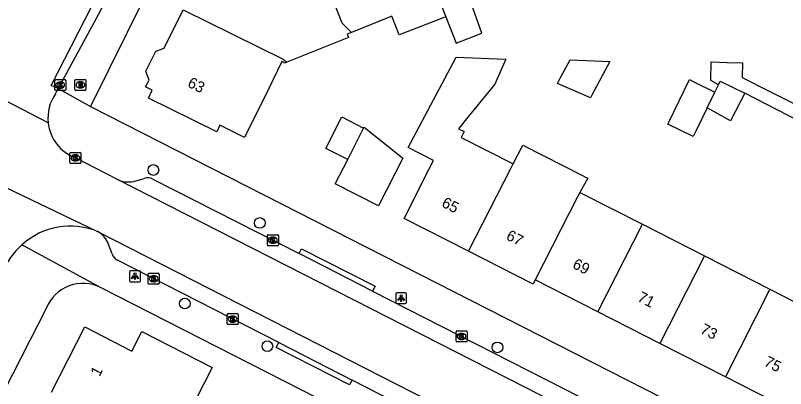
# Model space of a CAD drawing. Extents: x 160356 to 161355, y 381727 to 382845.
# Drawn here: x 161153.1 to 161223.5, y 382295.8 to 382329.8 of the extents above; entities that cross this region are included whole.
import ezdxf

# ---------------------------------------------------------------- set-up
doc = ezdxf.new("R2010")
doc.units = 0
for name, color, linetype in [('IMGEO_Boom', 7, 'Continuous'), ('IMGEO_Brandkraan', 7, 'Continuous'), ('IMGEO_Kolk', 7, 'Continuous'), ('IMGEO_Lichtpunt', 7, 'Continuous'), ('IMGEO_Pand', 7, 'Continuous'), ('IMGEO_Pand_nummerreeks', 7, 'Continuous'), ('IMGEO_Rijbaan_lokaal_open', 7, 'Continuous'), ('IMGEO_Voetpad_open', 7, 'Continuous')]:
    doc.layers.add(name, color=color, linetype=linetype)

msp = doc.modelspace()

# ---------------------------------------------------------------- linework, layer by layer
at = {"layer": 'IMGEO_Boom'}
for centre in [(161165.74, 382315.723), (161175.464, 382310.884), (161168.612, 382303.527), (161176.157, 382299.63), (161197.188, 382299.521)]:
    msp.add_circle(centre, 0.489, dxfattribs=at)
at = {"layer": 'IMGEO_Brandkraan'}
for p, q in [((161158.569, 382323.071), (161158.569, 382323.923)), ((161158.644, 382323.997), (161159.496, 382323.997)), ((161159.057, 382323.777), (161159.082, 382323.777)), ((161159.57, 382323.923), (161159.57, 382323.071)), ((161159.496, 382322.997), (161158.644, 382322.997)), ((161159.08, 382323.217), (161159.055, 382323.217))]:
    msp.add_line(p, q, dxfattribs=at)
for points in [[(161158.569, 382323.071), (161158.569, 382323.923)], [(161158.644, 382323.997), (161159.496, 382323.997)], [(161158.917, 382323.697), (161158.917, 382323.297), (161159.13, 382323.297)], [(161159.148, 382323.697), (161158.917, 382323.697)], [(161159.57, 382323.923), (161159.57, 382323.071)], [(161159.496, 382322.997), (161158.644, 382322.997)], [(161159.096, 382323.616), (161159.042, 382323.616), (161159.042, 382323.54)], [(161159.042, 382323.54), (161159.095, 382323.54)], [(161159.104, 382323.464), (161159.042, 382323.464), (161159.042, 382323.383)], [(161159.042, 382323.383), (161159.104, 382323.383)]]:
    msp.add_lwpolyline(points, dxfattribs=at)
for centre, radius, start, end in [((161158.646, 382323.921), 0.0765, 91.55205, 178.44795), ((161158.646, 382323.921), 0.0765, 91.55205, 178.44795), ((161159.152, 382323.552), 0.145, 59.4692, 91.53667), ((161159.177, 382323.599), 0.0922, 285.51372, 58.15012), ((161159.494, 382323.921), 0.0765, 1.55205, 88.44795), ((161159.494, 382323.921), 0.0765, 1.55205, 88.44795), ((161158.646, 382323.073), 0.0765, 181.55205, 268.44795), ((161158.646, 382323.073), 0.0765, 181.55205, 268.44795), ((161159.097, 382323.578), 0.0379, 267.82845, 90.93552), ((161159.105, 382323.423), 0.0404, 269.87594, 90.50774), ((161159.136, 382323.548), 0.251, 268.66757, 293.53466), ((161159.182, 382323.407), 0.105, 301.31148, 78.98903), ((161159.494, 382323.073), 0.0765, 271.55205, 358.44795), ((161159.494, 382323.073), 0.0765, 271.55205, 358.44795)]:
    msp.add_arc(centre, radius, start, end, dxfattribs=at)
for centre, major_axis, ratio, start_param, end_param in [((161159.056, 382323.497), (-0.387, 0.002), 0.722429, 4.712389, 7.853982), ((161159.081, 382323.497), (-0.39, 0.002), 0.717154, 1.570796, 4.712389)]:
    msp.add_ellipse(centre, major_axis=major_axis, ratio=ratio, start_param=start_param, end_param=end_param, dxfattribs=at)
at = {"layer": 'IMGEO_Kolk'}
for p, q in [((161156.722, 382323.057), (161156.722, 382323.909)), ((161156.797, 382323.983), (161157.649, 382323.983)), ((161157.21, 382323.763), (161157.235, 382323.763)), ((161157.723, 382323.909), (161157.723, 382323.057)), ((161157.649, 382322.983), (161156.797, 382322.983)), ((161157.233, 382323.203), (161157.208, 382323.203)), ((161158.112, 382316.402), (161158.112, 382317.254)), ((161158.187, 382317.328), (161159.039, 382317.328)), ((161158.6, 382317.108), (161158.625, 382317.108)), ((161159.113, 382317.254), (161159.113, 382316.402)), ((161159.039, 382316.328), (161158.187, 382316.328)), ((161158.623, 382316.548), (161158.598, 382316.548)), ((161176.16, 382308.885), (161176.16, 382309.737)), ((161176.235, 382309.811), (161177.087, 382309.811)), ((161176.648, 382309.591), (161176.673, 382309.591)), ((161177.161, 382309.737), (161177.161, 382308.885)), ((161176.671, 382309.031), (161176.646, 382309.031)), ((161177.087, 382308.811), (161176.235, 382308.811)), ((161165.261, 382305.366), (161165.261, 382306.218)), ((161165.336, 382306.292), (161166.188, 382306.292)), ((161165.749, 382306.072), (161165.774, 382306.072)), ((161166.262, 382306.218), (161166.262, 382305.366)), ((161165.772, 382305.512), (161165.747, 382305.512)), ((161166.188, 382305.292), (161165.336, 382305.292)), ((161172.56, 382302.603), (161173.412, 382302.603)), ((161172.485, 382301.677), (161172.485, 382302.529)), ((161172.973, 382302.383), (161172.998, 382302.383)), ((161173.486, 382302.529), (161173.486, 382301.677)), ((161173.412, 382301.603), (161172.56, 382301.603)), ((161172.996, 382301.823), (161172.971, 382301.823)), ((161193.408, 382300.094), (161193.408, 382300.946)), ((161193.483, 382301.02), (161194.335, 382301.02)), ((161193.896, 382300.8), (161193.921, 382300.8)), ((161194.409, 382300.946), (161194.409, 382300.094)), ((161194.335, 382300.02), (161193.483, 382300.02)), ((161193.919, 382300.24), (161193.894, 382300.24))]:
    msp.add_line(p, q, dxfattribs=at)
for points in [[(161156.722, 382323.057), (161156.722, 382323.909)], [(161156.797, 382323.983), (161157.649, 382323.983)], [(161157.043, 382323.683), (161157.166, 382323.683), (161157.166, 382323.532), (161157.296, 382323.683), (161157.46, 382323.683), (161157.314, 382323.532), (161157.467, 382323.283), (161157.315, 382323.283), (161157.23, 382323.447), (161157.166, 382323.38), (161157.166, 382323.283), (161157.043, 382323.283), (161157.043, 382323.683)], [(161157.723, 382323.909), (161157.723, 382323.057)], [(161157.649, 382322.983), (161156.797, 382322.983)], [(161158.112, 382316.402), (161158.112, 382317.254)], [(161158.187, 382317.328), (161159.039, 382317.328)], [(161158.433, 382317.028), (161158.556, 382317.028), (161158.556, 382316.877), (161158.686, 382317.028), (161158.85, 382317.028), (161158.704, 382316.877), (161158.857, 382316.628), (161158.705, 382316.628), (161158.62, 382316.792), (161158.556, 382316.725), (161158.556, 382316.628), (161158.433, 382316.628), (161158.433, 382317.028)], [(161159.113, 382317.254), (161159.113, 382316.402)], [(161159.039, 382316.328), (161158.187, 382316.328)], [(161176.16, 382308.885), (161176.16, 382309.737)], [(161176.235, 382309.811), (161177.087, 382309.811)], [(161177.161, 382309.737), (161177.161, 382308.885)], [(161176.481, 382309.511), (161176.604, 382309.511), (161176.604, 382309.36), (161176.734, 382309.511), (161176.898, 382309.511), (161176.752, 382309.36), (161176.905, 382309.111), (161176.753, 382309.111), (161176.668, 382309.275), (161176.604, 382309.208), (161176.604, 382309.111), (161176.481, 382309.111), (161176.481, 382309.511)], [(161177.087, 382308.811), (161176.235, 382308.811)], [(161165.261, 382305.366), (161165.261, 382306.218)], [(161165.336, 382306.292), (161166.188, 382306.292)], [(161166.262, 382306.218), (161166.262, 382305.366)], [(161165.582, 382305.992), (161165.705, 382305.992), (161165.705, 382305.841), (161165.835, 382305.992), (161165.999, 382305.992), (161165.853, 382305.841), (161166.006, 382305.592), (161165.854, 382305.592), (161165.769, 382305.756), (161165.705, 382305.689), (161165.705, 382305.592), (161165.582, 382305.592), (161165.582, 382305.992)], [(161166.188, 382305.292), (161165.336, 382305.292)], [(161172.56, 382302.603), (161173.412, 382302.603)], [(161172.485, 382301.677), (161172.485, 382302.529)], [(161172.806, 382302.303), (161172.929, 382302.303), (161172.929, 382302.152), (161173.059, 382302.303), (161173.223, 382302.303), (161173.077, 382302.152), (161173.23, 382301.903), (161173.078, 382301.903), (161172.993, 382302.067), (161172.929, 382302), (161172.929, 382301.903), (161172.806, 382301.903), (161172.806, 382302.303)], [(161173.486, 382302.529), (161173.486, 382301.677)], [(161173.412, 382301.603), (161172.56, 382301.603)], [(161193.408, 382300.094), (161193.408, 382300.946)], [(161193.483, 382301.02), (161194.335, 382301.02)], [(161193.729, 382300.72), (161193.852, 382300.72), (161193.852, 382300.569), (161193.982, 382300.72), (161194.146, 382300.72), (161194, 382300.569), (161194.153, 382300.32), (161194.001, 382300.32), (161193.916, 382300.484), (161193.852, 382300.417), (161193.852, 382300.32), (161193.729, 382300.32), (161193.729, 382300.72)], [(161194.409, 382300.946), (161194.409, 382300.094)], [(161194.335, 382300.02), (161193.483, 382300.02)]]:
    msp.add_lwpolyline(points, dxfattribs=at)
for centre, start, end in [((161156.799, 382323.907), 91.55205, 178.44795), ((161156.799, 382323.907), 91.55205, 178.44795), ((161157.647, 382323.907), 1.55205, 88.44795), ((161157.647, 382323.907), 1.55205, 88.44795), ((161156.799, 382323.059), 181.55205, 268.44795), ((161156.799, 382323.059), 181.55205, 268.44795), ((161157.647, 382323.059), 271.55205, 358.44795), ((161157.647, 382323.059), 271.55205, 358.44795), ((161158.189, 382317.252), 91.55205, 178.44795), ((161158.189, 382317.252), 91.55205, 178.44795), ((161159.037, 382317.252), 1.55205, 88.44795), ((161159.037, 382317.252), 1.55205, 88.44795), ((161158.189, 382316.404), 181.55205, 268.44795), ((161158.189, 382316.404), 181.55205, 268.44795), ((161159.037, 382316.404), 271.55205, 358.44795), ((161159.037, 382316.404), 271.55205, 358.44795), ((161176.237, 382309.735), 91.55205, 178.44795), ((161176.237, 382309.735), 91.55205, 178.44795), ((161177.085, 382309.735), 1.55205, 88.44795), ((161177.085, 382309.735), 1.55205, 88.44795), ((161176.237, 382308.887), 181.55205, 268.44795), ((161176.237, 382308.887), 181.55205, 268.44795), ((161177.085, 382308.887), 271.55205, 358.44795), ((161177.085, 382308.887), 271.55205, 358.44795), ((161165.338, 382306.216), 91.55205, 178.44795), ((161165.338, 382306.216), 91.55205, 178.44795), ((161166.186, 382306.216), 1.55205, 88.44795), ((161166.186, 382306.216), 1.55205, 88.44795), ((161165.338, 382305.368), 181.55205, 268.44795), ((161165.338, 382305.368), 181.55205, 268.44795), ((161166.186, 382305.368), 271.55205, 358.44795), ((161166.186, 382305.368), 271.55205, 358.44795), ((161172.562, 382302.527), 91.55205, 178.44795), ((161172.562, 382302.527), 91.55205, 178.44795), ((161173.41, 382302.527), 1.55205, 88.44795), ((161173.41, 382302.527), 1.55205, 88.44795), ((161172.562, 382301.679), 181.55205, 268.44795), ((161172.562, 382301.679), 181.55205, 268.44795), ((161173.41, 382301.679), 271.55205, 358.44795), ((161173.41, 382301.679), 271.55205, 358.44795), ((161193.485, 382300.944), 91.55205, 178.44795), ((161193.485, 382300.944), 91.55205, 178.44795), ((161194.333, 382300.944), 1.55205, 88.44795), ((161194.333, 382300.944), 1.55205, 88.44795), ((161193.485, 382300.096), 181.55205, 268.44795), ((161193.485, 382300.096), 181.55205, 268.44795), ((161194.333, 382300.096), 271.55205, 358.44795), ((161194.333, 382300.096), 271.55205, 358.44795)]:
    msp.add_arc(centre, 0.0765, start, end, dxfattribs=at)
for centre, major_axis, ratio, start_param, end_param in [((161157.209, 382323.483), (-0.387, 0.002), 0.722429, 4.712389, 7.853982), ((161157.234, 382323.483), (-0.39, 0.002), 0.717154, 1.570796, 4.712389), ((161158.599, 382316.828), (-0.387, 0.002), 0.722429, 4.712389, 7.853982), ((161158.624, 382316.828), (-0.39, 0.002), 0.717154, 1.570796, 4.712389), ((161176.647, 382309.311), (-0.387, 0.002), 0.722429, 4.712389, 7.853982), ((161176.672, 382309.311), (-0.39, 0.002), 0.717154, 1.570796, 4.712389), ((161165.748, 382305.792), (-0.387, 0.002), 0.722429, 4.712389, 7.853982), ((161165.773, 382305.792), (-0.39, 0.002), 0.717154, 1.570796, 4.712389), ((161172.972, 382302.103), (-0.387, 0.002), 0.722429, 4.712389, 7.853982), ((161172.997, 382302.103), (-0.39, 0.002), 0.717154, 1.570796, 4.712389), ((161193.895, 382300.52), (-0.387, 0.002), 0.722429, 4.712389, 7.853982), ((161193.92, 382300.52), (-0.39, 0.002), 0.717154, 1.570796, 4.712389)]:
    msp.add_ellipse(centre, major_axis=major_axis, ratio=ratio, start_param=start_param, end_param=end_param, dxfattribs=at)
at = {"layer": 'IMGEO_Lichtpunt'}
for p, q in [((161163.56, 382306.418), (161163.56, 382305.611)), ((161163.56, 382306.418), (161163.56, 382305.611)), ((161164.462, 382306.513), (161163.654, 382306.513)), ((161164.462, 382306.513), (161163.654, 382306.513)), ((161164.556, 382305.611), (161164.556, 382306.418)), ((161164.556, 382305.611), (161164.556, 382306.418)), ((161163.654, 382305.517), (161164.462, 382305.517)), ((161163.654, 382305.517), (161164.462, 382305.517)), ((161187.889, 382304.418), (161187.889, 382303.611)), ((161187.889, 382304.418), (161187.889, 382303.611)), ((161188.791, 382304.513), (161187.983, 382304.513)), ((161188.791, 382304.513), (161187.983, 382304.513)), ((161188.885, 382303.611), (161188.885, 382304.418)), ((161188.885, 382303.611), (161188.885, 382304.418)), ((161187.983, 382303.517), (161188.791, 382303.517)), ((161187.983, 382303.517), (161188.791, 382303.517))]:
    msp.add_line(p, q, dxfattribs=at)
for points in [[(161163.934, 382306.082), (161163.973, 382306.054), (161163.785, 382305.792), (161163.747, 382305.819), (161163.934, 382306.082)], [(161164.146, 382306.054), (161164.184, 382306.081), (161164.371, 382305.819), (161164.332, 382305.791), (161164.146, 382306.054)], [(161164.036, 382306.034), (161164.083, 382306.034), (161164.083, 382305.712), (161164.036, 382305.712), (161164.036, 382306.034)], [(161188.263, 382304.082), (161188.302, 382304.054), (161188.114, 382303.792), (161188.076, 382303.819), (161188.263, 382304.082)], [(161188.365, 382304.034), (161188.412, 382304.034), (161188.412, 382303.712), (161188.365, 382303.712), (161188.365, 382304.034)], [(161188.475, 382304.054), (161188.513, 382304.081), (161188.7, 382303.819), (161188.661, 382303.791), (161188.475, 382304.054)]]:
    msp.add_lwpolyline(points, dxfattribs=at)
for centre in [(161164.059, 382306.216), (161188.388, 382304.216)]:
    msp.add_circle(centre, 0.0994, dxfattribs=at)
for centre, start, end in [((161163.654, 382306.418), 90, 180), ((161163.654, 382306.418), 90, 180), ((161164.462, 382306.418), 0, 90), ((161164.462, 382306.418), 0, 90), ((161163.654, 382305.611), 180, 270), ((161163.654, 382305.611), 180, 270), ((161164.462, 382305.611), 270, 0), ((161164.462, 382305.611), 270, 360), ((161187.983, 382304.418), 90, 180), ((161187.983, 382304.418), 90, 180), ((161188.791, 382304.418), 0, 90), ((161188.791, 382304.418), 0, 90), ((161187.983, 382303.611), 180, 270), ((161187.983, 382303.611), 180, 270), ((161188.791, 382303.611), 270, 0), ((161188.791, 382303.611), 270, 360)]:
    msp.add_arc(centre, 0.0946, start, end, dxfattribs=at)
at = {"layer": 'IMGEO_Pand'}
for points in [[(161187.736, 382341.749), (161192.48, 382329.718)], [(161183.862, 382328.294), (161183.001, 382329.143), (161179.389, 382338.305)], [(161192.48, 382329.718), (161193.425, 382327.321), (161195.754, 382328.218), (161194.815, 382330.873), (161195.863, 382331.385), (161195.601, 382332.184), (161199.293, 382333.536), (161198.675, 382335.265)], [(161177.936, 382325.564), (161177.763, 382325.494), (161177.488, 382325.63), (161176.279, 382323.184), (161174.062, 382318.701), (161171.826, 382319.807), (161171.529, 382319.207), (161165.287, 382322.293), (161165.641, 382323.008), (161165.029, 382323.31), (161165.34, 382323.939), (161165.061, 382324.762), (161165.963, 382326.586), (161166.733, 382326.847), (161168.472, 382330.365)], [(161168.472, 382330.365), (161177.598, 382325.847), (161177.936, 382325.564)], [(161192.48, 382329.718), (161192.321, 382329.657), (161188.197, 382328.076), (161187.522, 382329.763), (161183.862, 382328.294)], [(161183.862, 382328.294), (161183.459, 382328.132), (161183.58, 382327.833), (161177.936, 382325.564)], [(161194.55, 382308.297), (161188.654, 382311.3), (161190.911, 382315.762), (161191.336, 382316.597), (161189.037, 382317.768), (161193.411, 382326.032), (161197.968, 382325.835), (161196.962, 382323.555), (161194.484, 382320.542), (161193.624, 382319.496), (161194.15, 382319.228), (161193.882, 382318.702), (161198.627, 382316.284)], [(161205.815, 382322.557), (161205.683, 382322.31), (161202.677, 382323.637), (161202.928, 382324.106), (161203.833, 382325.793), (161207.47, 382325.643), (161205.815, 382322.557)], [(161216.374, 382321.417), (161215.359, 382319.322), (161215.18, 382318.955), (161215.09, 382318.769), (161212.758, 382319.899), (161212.849, 382320.085), (161214.74, 382323.988), (161215.133, 382323.768), (161217.061, 382322.833)], [(161217.391, 382323.515), (161217.544, 382323.83), (161219.812, 382322.73)], [(161217.061, 382322.833), (161217.391, 382323.515)], [(161216.374, 382321.417), (161217.061, 382322.833)], [(161219.812, 382322.73), (161218.51, 382320.221), (161216.374, 382321.417)], [(161183.499, 382316.685), (161181.513, 382317.696), (161182.975, 382320.567), (161184.957, 382319.557)], [(161184.957, 382319.557), (161185.001, 382319.644), (161188.532, 382316.81), (161186.322, 382312.454), (161182.37, 382314.46), (161183.499, 382316.685)], [(161183.499, 382316.685), (161184.957, 382319.557)], [(161198.627, 382316.284), (161199.501, 382318.001), (161204.96, 382315.221), (161205.175, 382315.112), (161205.44, 382314.977), (161204.733, 382313.68)], [(161194.55, 382308.297), (161198.438, 382315.933), (161198.627, 382316.284)], [(161204.733, 382313.68), (161204.517, 382313.284), (161200.646, 382305.681)], [(161204.733, 382313.68), (161210.449, 382310.766)], [(161206.373, 382302.763), (161210.449, 382310.766)], [(161210.449, 382310.766), (161216.111, 382307.88)], [(161200.646, 382305.681), (161200.445, 382305.294), (161194.55, 382308.297)], [(161216.111, 382307.88), (161212.035, 382299.879)], [(161216.111, 382307.88), (161222.102, 382304.827)], [(161206.373, 382302.763), (161200.646, 382305.681)], [(161222.102, 382304.827), (161218.027, 382296.827)], [(161222.102, 382304.827), (161227.669, 382301.989)], [(161212.035, 382299.879), (161206.373, 382302.763)], [(161156.43, 382295.424), (161159.482, 382301.384), (161163.772, 382299.187), (161164.681, 382300.96), (161171.107, 382297.667), (161167.231, 382290.103), (161164.723, 382291.389), (161164.637, 382291.222)], [(161218.027, 382296.827), (161212.035, 382299.879)], [(161223.595, 382293.99), (161218.027, 382296.827)]]:
    msp.add_lwpolyline(points, dxfattribs=at)
at = {"layer": 'IMGEO_Rijbaan_lokaal_open'}
for points in [[(161157.045, 382323.157), (161156.387, 382323.442), (161164.48, 382339.209)], [(161156.12, 382320.042), (161121.232, 382338.155)], [(161156.789, 382322.683), (161157.045, 382323.157)], [(161141.419, 382319.292), (161160.696, 382310.075)], [(161162.39, 382314.875), (161158.609, 382316.828)], [(161210.448, 382290.411), (161162.39, 382314.875)], [(161160.696, 382310.075), (161208.137, 382285.873)]]:
    msp.add_lwpolyline(points, dxfattribs=at)
for centre, radius, start, end in [((161159.991, 382320.467), 3.894, 145.30751, 186.26296), ((161159.986, 382320.465), 3.889, 186.24308, 249.26707), ((161158.138, 382303.959), 6.629, 67.29955, 131.88042), ((161158.116, 382303.973), 6.605, 131.82192, 158.90727)]:
    msp.add_arc(centre, radius, start, end, dxfattribs=at)
at = {"layer": 'IMGEO_Voetpad_open'}
for points in [[(161223.471, 382358.051), (161213.418, 382355.081), (161203.163, 382351.691), (161194.808, 382348.706), (161183.742, 382344.252), (161168.109, 382337.664), (161166.656, 382335.004), (161159.99, 382321.52)], [(161162.385, 382333.172), (161160.695, 382329.907), (161157.045, 382323.157)], [(161217.391, 382323.515), (161216.686, 382323.91), (161216.726, 382325.591), (161218.199, 382325.556), (161219.6, 382325.522), (161219.567, 382324.167), (161222.106, 382322.89), (161260.339, 382303.664), (161260.087, 382303.173), (161259.91, 382302.824)], [(161157.045, 382323.157), (161159.99, 382321.52)], [(161251.443, 382289.87), (161258.477, 382303.494), (161254.338, 382305.631), (161251.999, 382306.823), (161249.87, 382307.908), (161242.822, 382311.495), (161240.485, 382312.686), (161238.354, 382313.772), (161231.404, 382317.31), (161229.179, 382318.444), (161226.936, 382319.587), (161226.727, 382319.178), (161219.812, 382322.73)], [(161159.99, 382321.52), (161245.388, 382278.03)], [(161163.94, 382314.676), (161164.895, 382314.944)], [(161165.693, 382314.9), (161179.065, 382308.084)], [(161160.913, 382304.981), (161153.712, 382308.895)], [(161161.961, 382308.056), (161161.615, 382309.006)], [(161179.065, 382308.084), (161179.292, 382308.529), (161186.001, 382305.109), (161185.774, 382304.664)], [(161177.197, 382299.953), (161162.451, 382307.484)], [(161185.774, 382304.664), (161179.065, 382308.084)], [(161182.222, 382294.107), (161160.913, 382304.981)], [(161185.774, 382304.664), (161211.126, 382291.742)], [(161155.969, 382303.136), (161142.883, 382277.595)], [(161183.898, 382296.531), (161183.671, 382296.086), (161176.97, 382299.508), (161177.197, 382299.953)], [(161177.197, 382299.953), (161183.898, 382296.531)], [(161207.441, 382284.507), (161183.898, 382296.531)]]:
    msp.add_lwpolyline(points, dxfattribs=at)
for centre, radius, start, end in [((161163.454, 382317.029), 2.403, 243.70459, 281.66338), ((161165.248, 382314.093), 0.922, 61.14888, 112.53918), ((161159.62, 382308.22), 2.144, 21.49606, 59.87405), ((161162.908, 382308.371), 0.998, 198.42228, 242.74731), ((161159.285, 382301.796), 3.577, 62.9368, 157.9923)]:
    msp.add_arc(centre, radius, start, end, dxfattribs=at)

# ---------------------------------------------------------------- texts
at = {"layer": 'IMGEO_Pand_nummerreeks'}
for s, rotation, p in [('63', 333.69254, (161168.784, 382323.376)), ('65', 333.00796, (161192.009, 382312.419)), ('67', 333.00796, (161197.905, 382309.416)), ('69', 333.00796, (161203.97, 382306.815)), ('71', 333.00796, (161209.909, 382303.79)), ('73', 333.00796, (161215.647, 382300.866)), ('75', 333.00796, (161221.486, 382297.892)), ('1', 62.88737, (161160.814, 382296.788))]:
    msp.add_text(s, height=1, rotation=rotation, dxfattribs=at).set_placement(p)

doc.saveas('drawing.dxf')
